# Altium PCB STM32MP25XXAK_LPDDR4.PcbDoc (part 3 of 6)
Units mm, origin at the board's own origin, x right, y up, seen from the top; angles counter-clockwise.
Board outline 120 x 79.6 mm, 4 copper layers (Top Layer, Signal Layer 1, Signal Layer 2, Bottom Layer), stack 1.614 mm thick; 190 components, 143 nets, 1208 pads, 757 vias.
Unrouted connection lines stored in the file: 3.
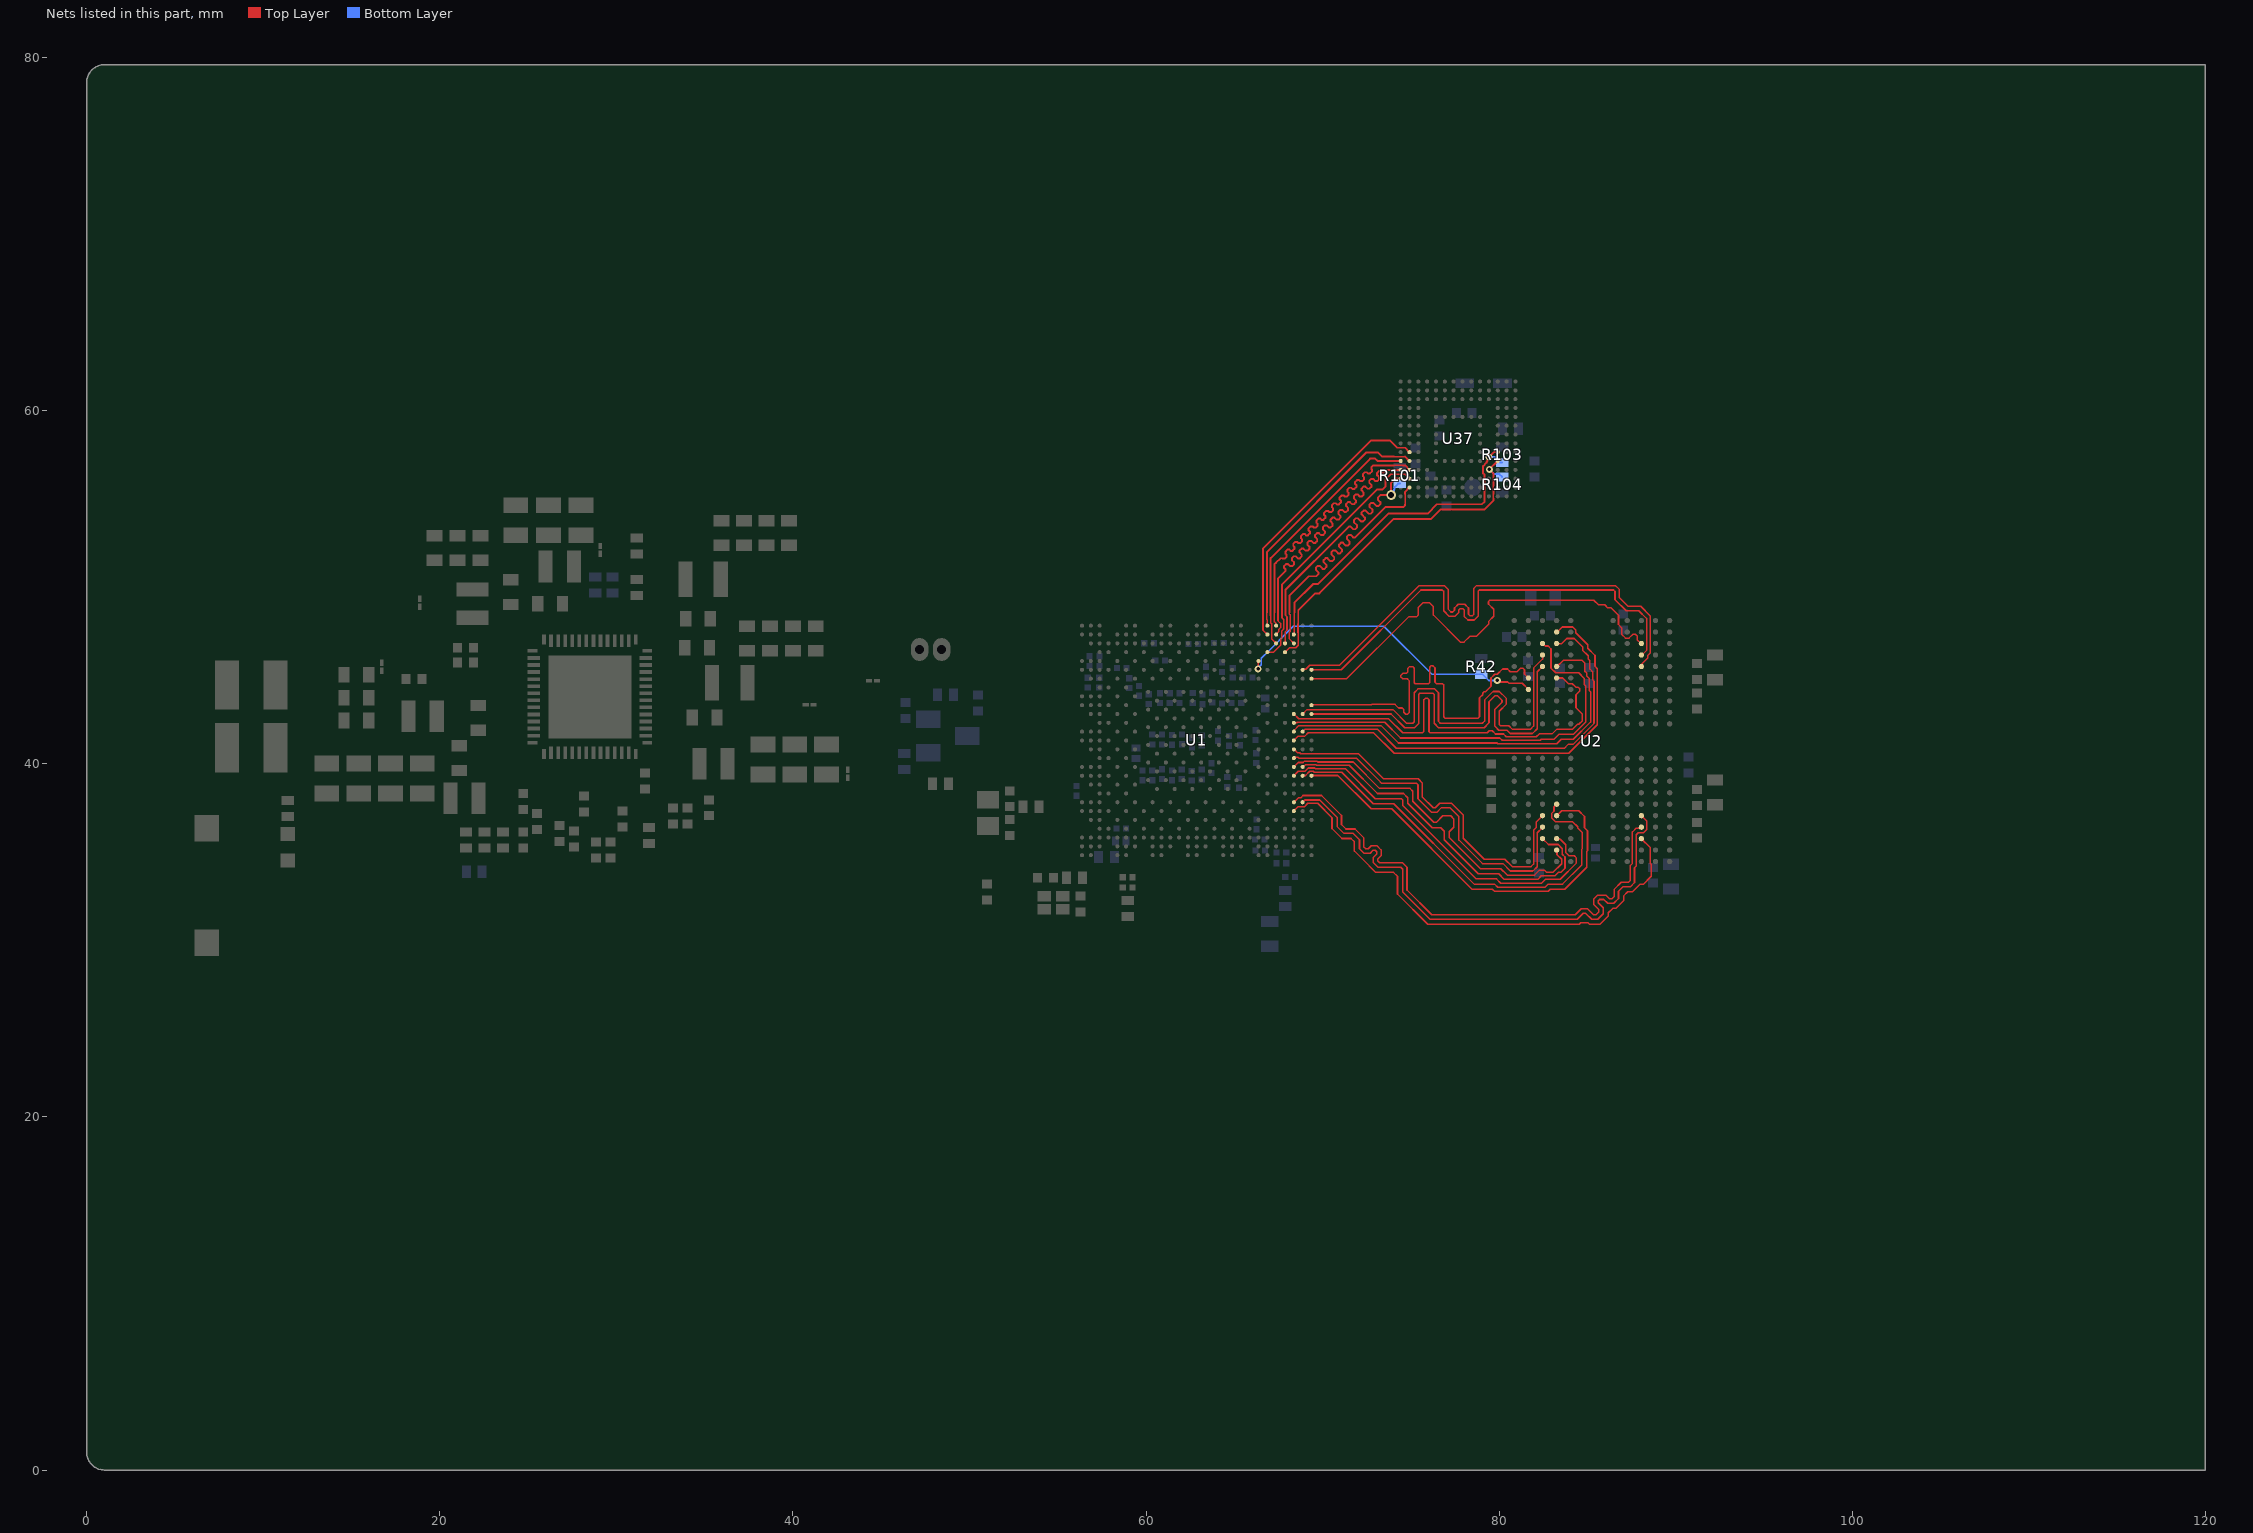
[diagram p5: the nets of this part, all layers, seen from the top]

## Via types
v1: diameter 0.55, hole 0.35, Top Layer to Bottom Layer, 277 vias
v2: diameter 0.4, hole 0.2, Top Layer to Bottom Layer, tented both sides, 229 vias
v3: diameter 0.5, hole 0.2, Top Layer to Bottom Layer, 146 vias
v4: diameter 0.4, hole 0.2, Top Layer to Bottom Layer, 105 vias

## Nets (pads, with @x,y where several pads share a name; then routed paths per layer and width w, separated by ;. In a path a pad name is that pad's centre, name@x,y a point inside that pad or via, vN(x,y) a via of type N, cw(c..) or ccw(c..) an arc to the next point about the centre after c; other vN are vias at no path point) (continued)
DDR_DQ11_B: U1.K27 U2.U11 | length 23.1
  Top Layer w0.09: U1.K27@69.377,43.329 69.388,43.34 72.76,43.34 72.785,43.365 74.106,43.365 74.305,43.166 74.514,43.166 74.604,43.076 74.604,42.916 74.709,42.81 74.817,42.81 74.903,42.896 74.903,44.715 74.801,44.817 74.539,44.817 74.441,44.915 74.441,45.021 74.554,45.134 74.755,45.134 74.835,45.214 74.835,45.415 74.929,45.509 75.106,45.509 75.194,45.421 75.194,44.6 75.259,44.535 75.994,44.535 76.065,44.606 76.065,45.473 76.145,45.553 76.244,45.553 76.369,45.428 76.369,44.616 76.438,44.546 76.788,44.546 76.86,44.474 76.86,42.666 76.937,42.59 78.805,42.59 78.89,42.675 78.89,43.739 79.072,43.921 79.072,44.007 79.16,44.095 79.246,44.095 79.543,44.392 79.543,44.861 79.756,45.074 ; 79.757,45.074 79.896,45.074 80.196,45.374 80.482,45.374 80.636,45.22 81.018,45.22 81.212,45.414 81.35,45.414 81.44,45.324 81.44,45.085 U2.U11@81.66,44.865
DDR_DQ12_A: U1.V26 U2.F9 | length 24
  Top Layer w0.09: U1.V26@68.875,39.325 68.889,39.339 69.035,39.339 69.271,39.575 69.479,39.575 69.525,39.529 71.083,39.529 72.872,37.74 74.033,37.74 78.583,33.19 78.607,33.19 79.737,33.19 79.918,33.01 82.602,33.01 82.782,33.19 83.598,33.19 84.671,34.263 84.671,35.154 84.72,35.203 84.72,36.094 84.451,36.363 84.451,36.43 84.168,36.713 83.209,36.713 82.975,36.947 82.975,37.183 83.112,37.32 83.112,37.567 U2.F9@83.26,37.715
DDR_DQ12_B: U1.L25 U2.U9 | length 24.7
  Top Layer w0.09: U1.L25@68.375,42.825 68.381,42.825 68.647,42.559 73.739,42.559 74.537,41.76 75.661,41.76 75.74,41.839 75.74,43.628 75.817,43.705 75.956,43.705 76.03,43.631 76.03,41.834 76.105,41.76 79.329,41.76 79.441,41.872 79.607,41.872 79.791,41.689 ; 79.792,41.689 80.248,41.689 80.408,41.529 82.109,41.529 82.275,41.695 83.003,41.695 83.277,41.969 84.169,41.969 84.445,42.244 84.517,42.244 84.719,42.446 84.719,42.814 84.355,43.178 84.355,43.916 84.569,44.13 84.569,44.254 84.476,44.347 84.354,44.347 84.352,44.349 84.336,44.349 84.145,44.54 83.927,44.54 83.602,44.865 U2.U9@83.26,44.865
DDR_DQ13_A: U1.V27 U2.E9 | length 23.7
  Top Layer w0.09: U1.V27@69.377,39.329 69.387,39.339 70.863,39.339 72.752,37.45 73.913,37.45 78.462,32.9 78.465,32.9 79.616,32.9 79.737,32.78 ; 79.738,32.78 82.782,32.78 82.902,32.9 83.718,32.9 84.961,34.143 84.961,35.027 85.01,35.075 85.01,36.214 84.839,36.385 84.839,37.024 84.513,37.35 83.545,37.35 U2.E9@83.26,37.065
DDR_DQ13_B: U1.N25 U2.V9 | length 23.2
  Top Layer w0.09: U1.N25@68.377,41.829 68.377,41.891 68.653,42.167 73.311,42.167 74.297,41.18 79.884,41.18 ; 79.886,41.18 79.921,41.144 83.272,41.144 83.517,41.389 84.204,41.389 85.184,42.369 85.184,44.071 85.1,44.155 85.1,44.832 84.977,44.955 84.977,45.126 84.854,45.249 84.854,45.713 84.698,45.869 83.648,45.869 83.273,45.494 U2.V9@83.259,45.494
DDR_DQ14_A: U1.V25 U2.C9 | length 21.7
  Top Layer w0.09: U1.V25@68.374,39.326 68.623,39.575 69.003,39.575 69.193,39.765 69.557,39.765 69.603,39.719 71.303,39.719 72.992,38.03 74.466,38.03 74.535,37.961 74.535,37.648 78.703,33.48 79.858,33.48 80.098,33.24 82.4,33.24 82.63,33.47 83.468,33.47 84.381,34.383 84.381,34.666 84.25,34.797 83.958,34.797 83.775,34.98 83.775,35.413 83.463,35.725 83.3,35.725 U2.C9@83.26,35.765
DDR_DQ14_B: U1.N26 U2.Y9 | length 24
  Top Layer w0.09: U1.N26@68.875,41.825 69.008,41.958 73.109,41.958 74.177,40.89 83.701,40.89 83.91,41.099 84.183,41.099 85.374,42.29 85.374,44.689 85.307,44.756 85.307,45.206 85.144,45.369 85.144,45.833 85.044,45.933 85.044,46.117 84.729,46.432 84.729,46.632 84.725,46.632 84.257,47.1 83.84,47.1 83.554,46.814 U2.Y9@83.26,46.815
DDR_DQ15_A: U1.U25 U2.B9 | length 20.8
  Top Layer w0.09: U1.U25@68.377,39.829 68.625,40.077 68.894,40.077 68.956,40.14 69.692,40.14 69.727,40.104 71.739,40.104 73.233,38.61 74.955,38.61 75.115,38.45 75.115,37.888 76.306,36.697 76.458,36.697 76.816,37.055 77.259,37.055 77.435,36.879 77.435,36.413 77.178,36.156 77.178,35.825 78.943,34.06 80.098,34.06 80.458,33.7 82.011,33.7 82.293,33.982 82.56,33.982 82.687,33.855 83.053,33.855 83.545,34.347 83.545,34.593 83.28,34.858 83.28,35.073 U2.B9@83.259,35.094
DDR_DQ15_B: U1.P25 U2.AA9 | length 25.7
  Top Layer w0.09: U1.P25@68.374,41.326 68.623,41.575 69.003,41.575 69.193,41.765 72.892,41.765 74.057,40.6 83.953,40.6 85.564,42.211 85.564,45.392 85.434,45.522 85.434,46.138 85.019,46.553 85.019,46.752 84.345,47.426 84.345,47.583 84.178,47.75 83.572,47.75 U2.AA9@83.266,47.444
DDR_DQMI0_A: U1.AB25 U2.C3 | length 28.3
  Top Layer w0.09: U1.AB25@68.375,37.325 68.375,37.336 68.614,37.575 68.979,37.575 69.169,37.765 69.722,37.765 70.535,36.952 70.535,36.336 71.1,35.771 71.617,35.771 71.806,35.582 71.806,35.066 72.238,34.633 73.02,33.851 74.022,33.851 74.246,33.627 74.246,32.625 75.961,30.91 84.543,30.91 84.628,30.995 85.037,30.995 85.122,30.91 85.714,30.91 86.19,31.386 86.19,31.567 86.434,31.811 86.615,31.811 87.053,32.249 87.053,32.512 87.295,32.754 87.558,32.754 87.975,33.171 88.159,33.171 88.619,33.632 88.619,34.303 88.559,34.363 88.559,35.266 U2.C3@88.06,35.765
DDR_DQMI0_B: U1.G27 U2.Y3 | length 25.8
  Top Layer w0.09: U1.G27@69.377,44.829 71.378,44.829 74.874,48.324 75.323,48.324 75.41,48.412 75.41,48.838 75.708,49.136 76.043,49.136 76.279,48.9 76.279,48.426 77.807,46.898 78.017,46.898 78.346,47.228 78.721,47.228 79.403,47.911 79.403,48.068 79.693,48.358 ; 79.694,48.358 79.694,48.761 79.398,49.057 79.398,49.19 79.478,49.27 85.368,49.27 ; 85.369,49.27 85.63,49.009 85.981,49.009 86.156,48.834 86.353,48.834 86.764,48.423 86.764,47.889 86.952,47.701 86.952,47.333 87.16,47.126 87.365,47.126 87.587,47.347 87.719,47.347 87.815,47.251 87.815,47.033 88.034,46.815 U2.Y3@88.06,46.815
DDR_DQMI1_A: U1.U26 U2.C10 | length 20.8
  Top Layer w0.09: U1.U26@68.875,39.825 68.91,39.825 69.038,39.953 69.624,39.953 69.663,39.914 71.519,39.914 73.113,38.32 74.586,38.32 74.825,38.081 74.825,37.768 76.209,36.384 76.689,36.384 76.888,36.185 76.888,35.705 78.823,33.77 79.978,33.77 80.278,33.47 82.204,33.47 82.394,33.66 83.161,33.66 83.351,33.85 83.492,33.85 83.735,34.093 83.735,34.722 83.584,34.873 83.584,35.194 83.347,35.431 82.794,35.431 U2.C10@82.46,35.765
DDR_DQMI1_B: U1.M25 U2.Y10 | length 23.7
  Top Layer w0.09: U1.M25@68.375,42.325 68.378,42.328 68.545,42.328 68.571,42.353 73.528,42.353 74.414,41.467 80.047,41.467 80.177,41.336 82.326,41.336 82.392,41.402 83.12,41.402 83.394,41.676 84.218,41.676 84.906,42.364 84.906,44.41 84.824,44.492 84.824,44.837 84.505,45.156 83.205,45.156 82.941,45.42 82.941,46.51 82.778,46.673 82.618,46.673 82.479,46.812 U2.Y10@82.463,46.812
DDR_DQS0_A_N: U1.AA26 U2.E3 | length 30.5
  Top Layer w0.09: U1.AA26@68.875,37.825 68.875,37.832 68.998,37.955 69.843,37.955 70.825,36.973 70.825,36.456 71.22,36.061 71.737,36.061 72.096,35.702 72.096,35.186 72.346,34.935 72.695,34.935 72.863,35.104 72.982,35.104 73.066,35.02 73.066,34.896 72.882,34.712 72.882,34.399 73.14,34.141 74.43,34.141 74.536,34.036 74.536,32.746 76.081,31.2 84.422,31.2 84.764,31.542 84.9,31.542 85.242,31.2 85.594,31.2 85.9,31.506 85.9,31.852 85.613,32.139 85.613,32.242 85.688,32.318 85.933,32.318 86.149,32.101 86.495,32.101 86.763,32.369 86.763,32.785 87.022,33.044 87.438,33.044 87.671,33.277 87.671,34.119 87.764,34.212 87.764,35.978 87.885,36.099 88.181,36.099 88.354,36.272 88.354,36.771 U2.E3@88.06,37.065
DDR_DQS0_A_P: U1.AA25 U2.D3 | length 29.9
  Top Layer w0.09: U1.AA25@68.375,37.825 68.62,38.07 68.76,38.07 68.894,38.205 69.947,38.205 71.075,37.077 71.075,36.56 71.324,36.311 71.841,36.311 72.346,35.806 72.346,35.289 72.449,35.185 72.591,35.185 72.76,35.354 73.086,35.354 73.316,35.124 73.316,34.792 73.132,34.608 73.132,34.503 73.243,34.391 74.534,34.391 74.786,34.139 74.786,32.849 76.185,31.45 84.319,31.45 84.66,31.792 85.004,31.792 85.345,31.45 85.49,31.45 85.65,31.609 85.65,31.748 85.363,32.035 85.363,32.346 85.584,32.568 86.037,32.568 86.253,32.351 86.392,32.351 86.513,32.473 86.513,32.888 86.919,33.294 87.334,33.294 87.421,33.381 87.421,34.223 87.554,34.356 87.554,36.145 87.758,36.349 87.937,36.349 88.003,36.415 U2.D3@88.06,36.415
DDR_DQS0_B_N: U1.F26 U2.V3 | length 29.3
  Top Layer w0.09: U1.F26@68.877,45.329 68.904,45.356 69.05,45.356 69.273,45.579 70.955,45.579 75.475,50.1 76.893,50.1 77.109,49.883 77.109,48.77 77.278,48.602 77.383,48.602 77.477,48.696 77.477,48.829 77.692,49.044 78.052,49.044 78.269,48.827 78.269,48.469 78.34,48.398 78.492,48.398 78.559,48.465 78.559,49.937 78.722,50.1 86.587,50.1 86.816,49.872 86.816,49.404 87.299,48.92 88.022,48.92 88.564,48.378 88.564,46.284 88.414,46.134 88.414,45.997 88.093,45.676 88.093,45.528 U2.V3@88.059,45.494
DDR_DQS0_B_P: U1.F27 U2.W3 | length 27.5
  Top Layer w0.09: U1.F27@69.377,45.329 71.058,45.329 75.579,49.85 76.789,49.85 ; 76.795,49.843 76.859,49.78 76.859,48.667 77.174,48.352 77.487,48.352 77.727,48.592 77.727,48.726 77.795,48.794 77.949,48.794 78.019,48.724 78.019,48.366 78.236,48.148 78.595,48.148 78.809,48.362 78.809,49.777 78.882,49.85 86.484,49.85 86.566,49.768 86.566,49.3 87.196,48.67 87.918,48.67 88.354,48.234 88.354,46.427 88.071,46.144 U2.W3@88.059,46.144
DDR_DQS1_A_N: U1.R25 U2.E10 | length 20.8
  Top Layer w0.09: U1.R25@68.375,40.825 68.392,40.825 68.584,40.633 68.713,40.633 68.771,40.575 72.031,40.575 73.456,39.15 75.427,39.15 75.655,38.922 75.655,38.127 76.271,37.511 76.377,37.511 76.638,37.772 77.306,37.772 77.975,37.103 77.975,35.792 79.167,34.6 80.32,34.6 ; 80.321,34.601 80.742,34.18 81.812,34.18 81.954,34.322 81.954,36.243 82.104,36.393 82.104,36.709 U2.E10@82.46,37.065
DDR_DQS1_A_P: U1.T25 U2.D10 | length 20.4
  Top Layer w0.09: U1.T25@68.375,40.325 68.413,40.325 68.471,40.383 68.61,40.383 68.668,40.325 71.928,40.325 73.28,38.973 73.353,38.9 75.323,38.9 75.405,38.818 75.405,38.024 76.168,37.261 76.481,37.261 76.742,37.522 77.202,37.522 77.725,36.999 77.725,35.689 79.063,34.35 80.217,34.35 ; 80.218,34.351 80.638,33.93 81.916,33.93 82.164,34.178 82.164,36.099 U2.D10@82.459,36.394
DDR_DQS1_B_N: U1.L27 U2.V10 | length 24.1
  Top Layer w0.09: U1.L27@69.377,42.825 73.816,42.825 ; 73.827,42.825 73.883,42.825 74.658,42.05 75.208,42.05 75.443,42.285 75.443,43.927 75.511,43.995 76.251,43.995 76.32,43.926 76.32,42.298 76.569,42.05 79.156,42.05 79.43,42.324 79.43,43.515 79.765,43.85 ; 79.766,43.85 79.912,43.85 80.167,43.596 80.167,43.491 79.764,43.088 79.764,42.127 79.984,41.907 80.447,41.907 80.633,41.72 81.89,41.72 82.164,41.994 82.164,45.219 U2.V10@82.46,45.515
DDR_DQS1_B_P: U1.L26 U2.W10 | length 25.1
  Top Layer w0.09: U1.L26@68.877,42.829 68.879,42.829 69.125,43.075 73.986,43.075 74.761,42.3 75.105,42.3 75.193,42.388 75.193,44.031 75.407,44.245 76.355,44.245 76.57,44.03 76.57,42.402 76.672,42.3 79.052,42.3 79.18,42.427 79.18,43.618 79.662,44.1 ; 79.663,44.1 80.016,44.1 80.417,43.699 80.417,43.387 80.014,42.984 80.014,42.23 80.088,42.157 80.55,42.157 80.737,41.97 81.786,41.97 81.954,42.138 81.954,45.427 82.464,45.937 82.464,46.161 U2.W10@82.46,46.165
DDR_RESETN: R42.2 U1.E21 U2.T11 | length 18.5
  Top Layer w0.09: v2(66.35,45.375) 66.369,45.394 U1.E21@66.369,45.819 ; v4@79.881,44.707 79.994,44.707 80.065,44.636 80.492,44.636 80.562,44.565 81.31,44.565 U2.T11@81.66,44.215
  Bottom Layer w0.09: v2@66.35,45.35 v2@66.35,45.434 ; v2@66.351,45.429 66.53,45.608 66.53,45.984 66.732,46.186 66.738,46.186 68.347,47.795 73.474,47.795 76.199,45.069 79.066,45.069 79.415,44.719 v4@79.895,44.719
  other v4: 79.895,44.725
eMMC.SDMMC2_CK: R103.1 U1.B25 U37.M6 | length 19.1
  Top Layer w0.09: U1.B25@68.375,47.325 68.402,47.352 68.402,48.575 ; 79.175,55.037 79.175,55.273 ; 79.175,55.537 79.175,55.773 ; 79.175,56.037 79.175,56.273
  Top Layer w0.11: 68.402,48.575 68.402,49.127 69.459,50.184 69.734,50.184 73.725,54.175 75.95,54.175 76.481,54.706 79.022,54.706 79.175,54.858 79.175,55.037 ; 79.175,55.273 79.175,55.405 ; 79.175,55.407 79.175,55.537 ; 79.175,55.773 79.175,55.905 ; 79.175,55.907 79.175,56.037 ; 79.175,56.273 79.175,56.372 79.095,56.452 79.095,56.87 79.281,57.056 v2(79.425,57.375) 79.705,57.655 U37.M6@79.925,57.655
  Bottom Layer w0.11: v2(79.425,57.375) 79.762,57.375 80.076,57.061 R103.1@80.171,57.061
eMMC.SDMMC2_CMD: R104.1 U1.D24 U37.M5 | length 20
  Top Layer w0.09: U1.D24@67.875,46.325 68.125,46.575 68.479,46.575 68.625,46.721 68.625,47.429 68.615,47.439 68.615,47.453 ; 79.675,55.037 79.675,55.273 ; 79.675,55.537 79.675,55.773 ; 79.675,56.037 79.675,56.273
  Top Layer w0.11: 68.616,47.451 68.615,47.453 68.615,47.933 68.625,47.943 68.625,48.699 69.588,49.662 69.816,49.662 74.029,53.875 76.15,53.875 76.674,54.399 79.162,54.399 79.675,54.911 79.675,55.037 ; 79.675,55.273 79.675,55.405 ; 79.675,55.407 79.675,55.537 ; 79.675,55.773 79.675,55.905 ; 79.675,55.907 79.675,56.037 ; 79.675,56.273 79.675,56.46 v2(79.45,56.685) U37.M5@79.92,57.155
  Bottom Layer w0.11: v2(79.45,56.685) 79.724,56.411 80.019,56.411 R104.1@80.175,56.255
eMMC.SDMMC2_D0: R101.1 U1.C24 U37.A3 | length 16
  Top Layer w0.09: U1.C24@67.875,46.825 67.88,46.83 67.88,47.467 67.985,47.572 67.985,48.335 67.902,48.418 67.902,48.575
  Top Layer w0.11: 67.902,48.575 67.902,49.85 71.229,53.177 71.487,53.435 71.597,53.435 71.743,53.289 71.852,53.289 71.962,53.399 71.962,53.508 71.778,53.692 71.778,53.801 71.888,53.911 71.998,53.911 72.181,53.727 72.291,53.727 72.4,53.837 72.4,53.947 72.217,54.13 72.217,54.24 72.326,54.349 72.436,54.349 72.62,54.166 72.729,54.166 72.839,54.275 72.839,54.385 72.655,54.569 72.655,54.678 72.765,54.788 72.874,54.788 73.058,54.604 73.168,54.604 73.277,54.714 73.277,54.823 73.131,54.969 73.131,55.079 73.279,55.227 v1(73.884,55.227) 73.884,55.909 74.13,56.155 U37.A3@74.425,56.155
  Bottom Layer w0.11: v1(73.884,55.227) 73.884,55.34 74.056,55.512 74.056,55.556 74.08,55.58 74.08,55.675 74.28,55.875 R101.1@74.375,55.875
eMMC.SDMMC2_D1: U1.B23 U37.A4 | length 18.8
  Top Layer w0.09: U1.B23@67.375,47.325 67.375,47.357 67.52,47.502 67.52,47.616 67.625,47.721 67.625,47.952 67.479,48.098 67.479,48.575
  Top Layer w0.11: 67.479,48.575 67.479,50.504 67.856,50.881 67.895,50.92 67.895,51.03 67.824,51.101 67.824,51.21 67.934,51.32 68.044,51.32 68.165,51.199 68.274,51.199 68.384,51.308 68.384,51.418 68.263,51.539 68.263,51.649 68.372,51.758 68.482,51.758 68.603,51.637 68.713,51.637 68.822,51.747 68.822,51.856 68.701,51.977 68.701,52.087 68.811,52.197 68.92,52.197 69.042,52.075 69.151,52.075 69.261,52.185 69.261,52.295 69.14,52.416 69.14,52.525 69.249,52.635 69.359,52.635 69.48,52.514 69.59,52.514 69.699,52.623 69.699,52.733 69.578,52.854 69.578,52.964 69.688,53.073 69.797,53.073 69.918,52.952 70.028,52.952 70.138,53.062 70.138,53.171 70.016,53.293 70.016,53.402 70.126,53.512 70.236,53.512 70.357,53.391 70.466,53.391 70.576,53.5 70.576,53.61 70.455,53.731 70.455,53.841 70.564,53.95 70.674,53.95 70.795,53.829 70.905,53.829 71.014,53.939 71.014,54.048 70.893,54.169 70.893,54.279 71.003,54.389 71.112,54.389 71.234,54.267 71.343,54.267 71.453,54.377 71.453,54.487 71.332,54.608 71.332,54.718 71.441,54.827 71.551,54.827 71.672,54.706 71.782,54.706 71.891,54.815 71.891,54.925 71.77,55.046 71.77,55.156 71.88,55.266 71.989,55.266 72.11,55.144 72.22,55.144 72.33,55.254 72.33,55.363 72.208,55.485 72.208,55.594 72.318,55.704 72.428,55.704 72.549,55.583 72.658,55.583 72.768,55.692 72.768,55.802 72.647,55.923 72.647,56.033 72.756,56.142 72.866,56.142 72.987,56.021 73.097,56.021 73.206,56.131 73.206,56.24 73.085,56.362 73.085,56.471 73.195,56.581 73.304,56.581 73.375,56.51 73.485,56.51 73.536,56.561 73.63,56.655 U37.A4@74.425,56.655
eMMC.SDMMC2_D2: U1.C23 U37.A5 | length 14.7
  Top Layer w0.09: 67.055,48.395 67.055,47.999 67.125,47.929 67.125,47.075 U1.C23@67.375,46.825
  Top Layer w0.11: 67.054,48.395 67.057,48.398 67.057,51.657 72.691,57.291 72.984,57.291 73.12,57.155 74.056,57.155 U37.A5@74.425,57.155
eMMC.SDMMC2_D3: U1.C25 U37.B2 | length 15.5
  Top Layer w0.09: 68.125,48.575 68.125,48.489 68.165,48.449 68.165,47.498 68.125,47.458 68.125,47.075 U1.C25@68.375,46.825 ; 74.675,54.705 74.675,55.273
  Top Layer w0.11: 68.125,48.575 68.125,49.525 69.225,50.625 69.647,50.625 69.723,50.702 69.762,50.741 69.762,50.85 69.621,50.991 69.621,51.101 69.731,51.211 69.84,51.211 70.004,51.046 70.114,51.046 70.224,51.156 70.224,51.266 70.059,51.43 70.059,51.539 70.169,51.649 70.279,51.649 70.443,51.485 70.552,51.485 70.662,51.594 70.662,51.704 70.498,51.868 70.498,51.978 70.607,52.087 70.717,52.087 70.881,51.923 70.991,51.923 71.1,52.033 71.1,52.142 70.936,52.307 70.936,52.416 71.046,52.526 71.155,52.526 71.32,52.362 71.429,52.362 71.539,52.471 71.539,52.581 71.375,52.745 71.375,52.855 71.484,52.964 71.594,52.964 71.735,52.823 71.845,52.823 71.887,52.865 73.582,54.56 74.596,54.56 74.675,54.639 74.675,54.705 ; 74.675,55.273 74.675,55.405 U37.B2@74.925,55.655
eMMC.SDMMC2_D4: U1.D22 U37.B3 | length 14.7
  Top Layer w0.09: U1.D22@66.902,46.352 U1.D22@66.875,46.325 67.229,46.325 67.625,46.721 67.625,47.075 67.7,47.15 67.7,47.541 67.805,47.647 67.805,48.17 67.7,48.275 ; 74.056,56.405 74.543,56.405
  Top Layer w0.11: 67.7,48.275 67.692,48.283 67.692,50.142 73.1,55.55 73.4,55.55 73.575,55.725 73.575,56.125 73.855,56.405 74.056,56.405 ; 74.543,56.405 74.675,56.405 U37.B3@74.925,56.155
eMMC.SDMMC2_D5: U1.A23 U37.B4 | length 17.3
  Top Layer w0.09: 67.267,48.575 67.267,48.055 67.349,47.973 67.349,47.851 U1.A23@67.375,47.825 ; 74.056,56.905 74.543,56.905
  Top Layer w0.11: 67.267,48.575 67.267,51.292 67.362,51.387 67.621,51.646 67.73,51.646 67.75,51.625 67.86,51.625 67.97,51.735 67.97,51.845 67.901,51.913 67.901,52.022 68.011,52.132 68.121,52.132 68.189,52.064 68.298,52.064 68.408,52.173 68.408,52.283 68.34,52.351 68.34,52.461 68.449,52.57 68.559,52.57 68.627,52.502 68.737,52.502 68.846,52.612 68.846,52.721 68.778,52.79 68.778,52.899 68.888,53.009 68.997,53.009 69.066,52.941 69.175,52.941 69.285,53.05 69.285,53.16 69.217,53.228 69.217,53.338 69.326,53.447 69.436,53.447 69.504,53.379 69.614,53.379 69.723,53.489 69.723,53.598 69.655,53.666 69.655,53.776 69.765,53.886 69.874,53.886 69.942,53.817 70.052,53.817 70.162,53.927 70.162,54.037 70.093,54.105 70.093,54.214 70.203,54.324 70.313,54.324 70.381,54.256 70.49,54.256 70.6,54.365 70.6,54.475 70.532,54.543 70.532,54.653 70.641,54.762 70.751,54.762 70.819,54.694 70.929,54.694 71.038,54.804 71.038,54.913 70.97,54.982 70.97,55.091 71.08,55.201 71.189,55.201 71.258,55.133 71.367,55.133 71.477,55.242 71.477,55.352 71.409,55.42 71.409,55.53 71.518,55.639 71.628,55.639 71.696,55.571 71.806,55.571 71.915,55.681 71.915,55.79 71.847,55.858 71.847,55.968 71.957,56.078 72.066,56.078 72.134,56.01 72.244,56.01 72.354,56.119 72.354,56.229 72.285,56.297 72.285,56.406 72.395,56.516 72.505,56.516 72.573,56.448 72.682,56.448 72.792,56.558 72.792,56.667 72.772,56.687 72.772,56.797 72.88,56.905 72.912,56.905 74.056,56.905 ; 74.543,56.905 74.675,56.905 U37.B4@74.925,56.655
eMMC.SDMMC2_D6: U1.A22 U37.B5 | length 14.8
  Top Layer w0.09: 66.847,48.356 66.847,48.176 66.875,48.148 U1.A22@66.875,47.825 ; 74.056,57.405 74.675,57.405
  Top Layer w0.096: 66.847,48.356 66.847,48.575
  Top Layer w0.11: 66.847,48.575 66.847,51.997 72.49,57.64 73.14,57.64 73.375,57.405 74.056,57.405 ; 74.675,57.405 U37.B5@74.925,57.155
eMMC.SDMMC2_D7: U1.B22 U37.B6 | length 16.1
  Top Layer w0.09: 66.625,48.575 66.625,47.575 U1.B22@66.875,47.325 ; 74.307,57.905 74.543,57.905
  Top Layer w0.11: 66.625,48.575 66.625,52.197 72.738,58.31 73.836,58.31 74.241,57.905 74.307,57.905 ; 74.543,57.905 74.675,57.905 U37.B6@74.925,57.655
